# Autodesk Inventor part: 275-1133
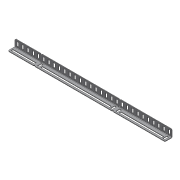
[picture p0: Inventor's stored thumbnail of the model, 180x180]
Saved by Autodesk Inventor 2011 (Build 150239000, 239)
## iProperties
Company: Autodesk Inc.
Created: 2005-08
Part Number: 275-1133
Document SubType Name: Sheet Metal
Designer: Autodesk Inc.
Density: 1 g/cm^3
Sheet Metal Rule: Default
Catalog Web Link: http://www.vexrobotics.com/products/accessories/structure/segmented-angle.html
Description: VEX angle (inverted) with holes and slots identical to the standard VEX kit. Can be cut to 5, 10, 15, 20 or 25 hole lengths.
Vendor: Innovation First, Inc.
Author: Autodesk Inc.
Title: VEX Robotics Kit of Parts
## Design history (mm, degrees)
node "Face1"
  sketch "Sketch1"
    geometry: L1 (-186.436, 13.081)-(-181.864, 13.081); L2 (-181.864, 13.081)-(-181.864, 3.302); L3 (-181.864, 3.302)-(-186.436, 3.302); L4 (-186.436, 3.302)-(-186.436, 13.081); L5 (-190.5, 14.605)-(-190.5, 0); L6 (190.5, 14.605)-(190.5, 0); L7 (-188.595, 16.51)-(-128.905, 16.51); L8 (-190.5, 0)-(190.5, 0); L9 (-127, 14.605)-(-127, 0); L10 (-127, 14.605)-(-128.905, 16.51); L11 (-188.595, 16.51)-(-190.5, 14.605); L12 (-173.736, 3.302)-(-173.736, 13.081); L13 (-169.164, 3.302)-(-173.736, 3.302); L14 (-169.164, 13.081)-(-169.164, 3.302); L15 (-173.736, 13.081)-(-169.164, 13.081); L16 (-161.036, 3.302)-(-161.036, 13.081); L17 (-156.464, 3.302)-(-161.036, 3.302); L18 (-156.464, 13.081)-(-156.464, 3.302); L19 (-161.036, 13.081)-(-156.464, 13.081); L20 (-148.336, 3.302)-(-148.336, 13.081); L21 (-143.764, 3.302)-(-148.336, 3.302); L22 (-143.764, 13.081)-(-143.764, 3.302); L23 (-148.336, 13.081)-(-143.764, 13.081); L24 (-135.636, 3.302)-(-135.636, 13.081); L25 (-131.064, 3.302)-(-135.636, 3.302); L26 (-131.064, 13.081)-(-131.064, 3.302); L27 (-135.636, 13.081)-(-131.064, 13.081); L28 (-122.936, 3.302)-(-122.936, 13.081); L29 (-118.364, 3.302)-(-122.936, 3.302); L30 (-118.364, 13.081)-(-118.364, 3.302); L31 (-122.936, 13.081)-(-118.364, 13.081); L32 (-110.236, 3.302)-(-110.236, 13.081); L33 (-105.664, 3.302)-(-110.236, 3.302); L34 (-105.664, 13.081)-(-105.664, 3.302); L35 (-110.236, 13.081)-(-105.664, 13.081); L36 (-97.536, 3.302)-(-97.536, 13.081); L37 (-92.964, 3.302)-(-97.536, 3.302); L38 (-92.964, 13.081)-(-92.964, 3.302); L39 (-97.536, 13.081)-(-92.964, 13.081); L40 (-84.836, 3.302)-(-84.836, 13.081); L41 (-80.264, 3.302)-(-84.836, 3.302); L42 (-80.264, 13.081)-(-80.264, 3.302); L43 (-84.836, 13.081)-(-80.264, 13.081); L44 (-72.136, 3.302)-(-72.136, 13.081); L45 (-67.564, 3.302)-(-72.136, 3.302); L46 (-67.564, 13.081)-(-67.564, 3.302); L47 (-72.136, 13.081)-(-67.564, 13.081); L48 (-59.436, 3.302)-(-59.436, 13.081); L49 (-54.864, 3.302)-(-59.436, 3.302); L50 (-54.864, 13.081)-(-54.864, 3.302); L51 (-59.436, 13.081)-(-54.864, 13.081); L52 (-46.736, 3.302)-(-46.736, 13.081); L53 (-42.164, 3.302)-(-46.736, 3.302); L54 (-42.164, 13.081)-(-42.164, 3.302); L55 (-46.736, 13.081)-(-42.164, 13.081); L56 (-34.036, 3.302)-(-34.036, 13.081); L57 (-29.464, 3.302)-(-34.036, 3.302); L58 (-29.464, 13.081)-(-29.464, 3.302); L59 (-34.036, 13.081)-(-29.464, 13.081); L60 (-21.336, 3.302)-(-21.336, 13.081); L61 (-16.764, 3.302)-(-21.336, 3.302); L62 (-16.764, 13.081)-(-16.764, 3.302); L63 (-21.336, 13.081)-(-16.764, 13.081); L64 (-8.636, 3.302)-(-8.636, 13.081)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; 6 further points
    constraints: 268 end point, 10 point on line, 5 parallel, 5 perpendicular, 2 horizontal, 2 symmetric about line, 1 coincident, 1 midpoint, 232 other
    dimensions: "d1" = 4.064 distance between parallel lines of L4 L5; "d2" = 9.779 distance between parallel lines of L3 L1; "d3" = 4.572 distance of L1.start L1.end; "d12" = 16.51 distance of point (-190.5, 16.51) L5.end; "d14" = 1.905 distance of L9.start point (-127, 16.51); "d15" = 1.905 distance of L7.end point (-127, 16.51) (= d14); "d16" = 1.905 distance of L7.start point (-190.5, 16.51); "d17" = 1.905 distance of L5.start point (-190.5, 16.51) (= d16); "d20" = 12.7 distance of L3.end L12.start; "d26" = 1.905 distance of L130.start point (63.5, 16.51); "d27" = 1.905 distance of L129.end point (63.5, 16.51) (= d26); "d28" = 1.905 distance of L6.start point (190.5, 16.51); "d29" = 1.905 distance of L133.end point (190.5, 16.51) (= d28); "d86" = 63.5 distance between parallel lines of L9 L5; "d87" = 127 distance between parallel lines of L6 L130; "d88" = 3.429 distance between parallel lines of L7 L1; "d89" = 381 distance of L5.end L6.end
node "Flange1"
feature "Corner Chamfer1" dims "d38" = 1.905, "d39" = 6.35, angle "d40" = 45 deg
sketch "Sketch3"
  geometry: L1 (381, -13.741)-(381, 0) reference; L2 (0, 0)-(0, -13.741) reference; L3 (1.905, -15.646)-(379.095, -15.646) reference; L4 (3.302, -7.01)-(60.198, -7.01); L5 (60.198, -7.01)-(60.198, -11.582); L6 (60.198, -11.582)-(3.302, -11.582); L7 (3.302, -11.582)-(3.302, -7.01); L8 (63.5, -13.741)-(63.5, 0); L9 (63.5, -13.741)-(61.595, -15.646); L10 (63.5, -13.741)-(65.405, -15.646); L11 (67.564, -2.438)-(72.136, -2.438); L12 (72.136, -2.438)-(72.136, -12.217); L13 (72.136, -12.217)-(67.564, -12.217); L14 (67.564, -12.217)-(67.564, -2.438); L15 (75.184, -7.01)-(242.316, -7.01); L16 (242.316, -7.01)-(242.316, -11.582); L17 (242.316, -11.582)-(75.184, -11.582); L18 (75.184, -11.582)-(75.184, -7.01); L19 (245.364, -2.438)-(249.936, -2.438); L20 (249.936, -2.438)-(249.936, -12.217); L21 (249.936, -12.217)-(245.364, -12.217); L22 (245.364, -12.217)-(245.364, -2.438); L23 (254, 0)-(254, -13.741); L24 (252.095, -15.646)-(254, -13.741); L25 (255.905, -15.646)-(254, -13.741); L26 (258.064, -2.438)-(262.636, -2.438); L27 (262.636, -2.438)-(262.636, -12.217); L28 (262.636, -12.217)-(258.064, -12.217); L29 (258.064, -12.217)-(258.064, -2.438); L30 (265.684, -7.01)-(369.316, -7.01); L31 (369.316, -7.01)-(369.316, -11.582); L32 (369.316, -11.582)-(265.684, -11.582); L33 (265.684, -11.582)-(265.684, -7.01); L34 (372.364, -2.438)-(376.936, -2.438); L35 (376.936, -2.438)-(376.936, -12.217); L36 (376.936, -12.217)-(372.364, -12.217); L37 (372.364, -12.217)-(372.364, -2.438); L38 (0, 0)-(381, 0) reference; L39 (61.595, -15.646)-(65.405, -15.646); L40 (252.095, -15.646)-(255.905, -15.646); L41 (1.905, -15.646)-(0, -13.741) reference; 2 further points
  constraints: 72 end point, 18 parallel, 13 collinear, 7 horizontal, 7 perpendicular, 4 point on line, 2 symmetric about line
  dimensions: "d41" = 3.302 distance between parallel lines of L2 L7; "d42" = 4.064 distance between parallel lines of L3 L6; "d43" = 4.572 distance between parallel lines of L4 L6; "d45" = 1.905 distance of L8.start point (63.5, -15.646); "d46" = 1.905 distance of L9.end point (63.5, -15.646) (= d45); "d48" = 4.064 distance between parallel lines of L14 L8; "d49" = 4.572 distance of L11.start L11.end; "d50" = 3.429 distance between parallel lines of L3 L13; "d51" = 9.779 distance of L11.end L12.end; "d52" = 3.048 distance between parallel lines of L18 L12; "d54" = 177.8 distance between parallel lines of L14 L22; "d55" = 3.048 distance between parallel lines of L22 L16; "d56" = 4.572 distance of L20.end L21.end; "d58" = 1.905 distance of L24.start point (254, -15.646); "d59" = 1.905 distance of L23.end point (254, -15.646) (= d58); "d61" = 4.064 distance between parallel lines of L23 L20; "d62" = 4.064 distance between parallel lines of L29 L23; "d63" = 4.572 distance between parallel lines of L29 L27; "d64" = 3.048 distance between parallel lines of L33 L27; "d65" = 4.064 distance between parallel lines of L1 L35; "d67" = 3.048 distance between parallel lines of L31 L37; "d68" = 4.572 distance between parallel lines of L35 L37; "d81" = 3.302 distance between parallel lines of L8 L5; "d90" = 63.5 distance between parallel lines of L2 L8
cut "Cut1" sketch "Sketch3" dims "d69" = 1.27 (= Thickness), "d70" = 0
sketch "Sketch5"
  geometry: L1 (63.5, -13.741)-(65.405, -15.646) reference; L2 (0, 0)-(381, 0) reference; L3 (61.595, 1.118)-(63.5, -0.787); L4 (63.5, -0.787)-(65.405, 1.118); L5 (65.405, 1.118)-(63.5, 3.023); L6 (63.5, 3.023)-(61.595, 1.118); L7 (252.095, 1.118)-(254, -0.787); L8 (254, -0.787)-(255.905, 1.118); L9 (255.905, 1.118)-(254, 3.023); L10 (254, 3.023)-(252.095, 1.118); 5 further points
  constraints: 16 end point, 6 vertical alignment, 5 parallel, 3 perpendicular, 2 horizontal alignment
  dimensions: "d82" = 1.1176 distance from line of L2 L3.start; "d83" = 1.1176 distance from line of L2 L7.start
cut "Cut2" sketch "Sketch5" dims "d84" = 1.27 (= Thickness), "d85" = 0
body "Solid1"
face "Plate1" dims "Thickness" = 1.27
sketch "Sketch2"
  geometry: L1 (381, 0)-(381, 16.51); L2 (381, 16.51)-(0, 16.51); 2 other entities
  constraints: 4 end point, 4 other
face "Plate2" dims "d31" = 1.27 (= BendReliefWidth), "d33" = 2.54 (= MinimumRemnant), "d35" = 16.51, "d36" = 90 deg, "d37" = 0.8636, "Thickness" = 1.27
bend "Bend1" dims "d31" = 1.27 (= BendReliefWidth), "d32" = 0.635 (= BendReliefDepth), "d33" = 2.54 (= MinimumRemnant), "d34" = 1.27 (= BendRadius), "d35" = 16.51, "d36" = 90 deg, "d37" = 0.8636, "SeamGap" = 0.00508, "Thickness" = 1.27
other parameters: "BendRadius" = 1.27 (= Thickness), "BendReliefWidth" = 1.27 (= Thickness), "BendReliefDepth" = 0.635 (= 0.5 x Thickness), "CornerReliefSize" = 5.08 (= 4 x Thickness), "MinimumRemnant" = 2.54 (= 2 x Thickness), "TransitionRadius" = 1.27 (= BendRadius), "d23" = 25.4, "d30" = 1.27 (= BendRadius), "JacobiRadiusSize" = 1.27 (= Thickness), "GapSize" = 1.27 (= Thickness)
